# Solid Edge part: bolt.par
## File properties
Author: Robert a Rhodes jr
Template: NORMENG.PAR
Last saved by: CADCIM
Revision: 4
Application: Solid Edge
Density: 0 lbm/in^3
Accuracy: 0.99
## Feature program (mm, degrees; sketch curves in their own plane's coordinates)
sketch for "unnamed Protrusion 1" plane through (0, 0, 0) normal (0, 0, 1) x-axis (1, 0, 0)
  line (-4.445, 0) -> (-2.2089, 3.81)
  line (-2.2089, 3.81) -> (2.2089, 3.81)
  line (2.2089, 3.81) -> (4.445, 0)
  line (4.445, 0) -> (2.2089, -3.81)
  line (2.2089, -3.81) -> (-2.2089, -3.81)
  line (-2.2089, -3.81) -> (-4.445, 0)
extrude "unnamed Protrusion 1" add finite 5.08 along +normal
sketch for "unnamed RevolvedCutout 1" plane through (0, 0, 0) normal (0, -1, 0) x-axis (1, 0, 0)
  line (-3.1867, 5.08) -> (-4.445, 4.3535)
revolve "unnamed RevolvedCutout 1" cut finite 360 deg
sketch for "ExtrudedProtrusion_2" plane through (0, 0, 0) normal (0, 0, -1) x-axis (-0.506172, 0.862433, 0)
  circle centre (0, 0) radius 3.175
extrude "ExtrudedProtrusion_2" add finite 76.2 along +normal
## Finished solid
Body 1: solid body, 11 faces, 21 edges, 12 vertices.
  Faces by surface: plane 9, cone 1, cylinder 1
  Edges by curve: line 12, intersection 6, circle 3
Bounding box of the edges (mm): 8.890 x 7.620 x 81.280, from (-4.445, -3.81, -76.2) to (4.445, 3.81, 5.08).
Cylindrical faces by radius (mm): R3.175 x1
Conical faces (half-angle, radius in mm at the cone's reference point): 60 deg R3.1867 x1
Planar faces by outward normal: +y 1, +z 1, -y 1, -z 2, oblique 4
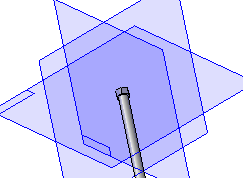
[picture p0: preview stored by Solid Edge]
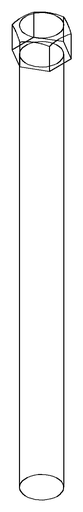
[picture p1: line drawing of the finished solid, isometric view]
